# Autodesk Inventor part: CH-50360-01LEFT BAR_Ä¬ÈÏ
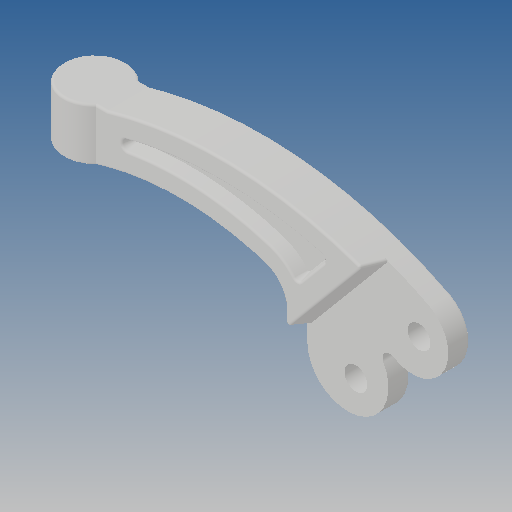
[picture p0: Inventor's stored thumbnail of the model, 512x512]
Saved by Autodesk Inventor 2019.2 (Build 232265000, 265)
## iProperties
Created: 2010-06
Part Number: CH-50360-01LEFT BAR_Ä¬ÈÏ
Material: Ogólny
Document SubType Name: Modeling
Designer: CADENGINEERING4
Density: 1 g/cm^3
Appearance: Domyślna
Author: CADENGINEERING4
Revision Number: ÈÎºÎ
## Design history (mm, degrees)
feature "NONE"
node "Bryła1"
